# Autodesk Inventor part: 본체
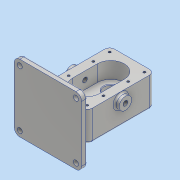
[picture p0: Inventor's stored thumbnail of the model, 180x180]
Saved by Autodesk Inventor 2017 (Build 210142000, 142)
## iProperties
Part Number: 본체
Material: 알루미늄 6061
Document SubType Name: Modeling
Designer: MRC
Density: 2.7 g/cm^3
Appearance: 알루미늄 - 평지
Mass: 1537.14 g
Surface Area: 869.879 cm^2
Volume: 569.31 cm^3
Author: MRC
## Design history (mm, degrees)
sketch "스케치1"
  geometry: L1 (40, -60)-(-40, -60); L2 (-40, -60)-(-40, 60); L3 (-40, 60)-(40, 60); L4 (40, 60)-(40, -60); L5 (40, -60)-(-40, 60); L6 (-40, -60)-(40, 60); 1 further point
  constraints: 12 end point, 2 midpoint, 2 parallel, 1 horizontal, 1 perpendicular
  dimensions: "d0" = 80 distance of L2.end L3.end; "d1" = 120 distance of L1.end L2.end
extrude "돌출1" new body sketch "스케치1" distance "d2" = 14; taper "d4" = 0 deg; dims "d3" = 39, "d5" = 0
fillet "모깎기1" dims "d6" = 9
sketch "스케치2"
  geometry: L1 (0, -22)-(0, 22); L2 (-24, -22)-(-24, 22); L3 (24, 22)-(24, -22); A1 r 24 centre (0, -22) between (-24, -22) and (24, -22); A2 r 24 centre (0, 22) between (24, 22) and (-24, 22); 1 further point
  constraints: 8 end point, 4 point on circle, 4 tangent, 2 centre point, 1 midpoint, 1 parallel, 1 vertical
  dimensions: "d7" = 24 radius of A2; "d8" = 44 distance of L3.start L3.end
extrude "돌출2" cut sketch "스케치2" distance "d9" = 29; taper "d10" = 0 deg
sketch "스케치4"
  geometry: C1 r 19 at (0, 22); A1 r 24 centre (0, 22) between (24, 22) and (-24, 22) reference; 1 further point
  constraints: 1 centre point, 1 concentric
  dimensions: "d11" = 38 diameter of C1
extrude "돌출3" join sketch "스케치4" distance "d12" = 17; taper "d13" = 0 deg
hole "구멍1" diameter "d16" = 17; stored, may be unused: countersink angle "d20" = 90 deg, drill point angle "d22" = 118 deg; dims "d14" = 10, "d15" = 10, "d17" = 6, "d18" = 28, "d19" = 7.3, "d21" = 8
sketch "스케치5"
  geometry: C1 r 8.5 at (0, 22) reference; C2 r 12.5 at (0, 22); C3 r 12.5 at (0, -22); A1 r 24 centre (0, -22) between (-24, -22) and (24, -22) reference; A2 r 24 centre (0, 22) between (24, 22) and (-24, 22) reference; 1 further point
  constraints: 2 centre point, 2 coincident
  dimensions: "d23" = 25 diameter of C2; "d24" = 25 diameter of C3
extrude "돌출4" cut sketch "스케치5" distance "d25" = 15; taper "d26" = 0 deg
fillet "모깎기2" dims "d27" = 0.5
chamfer "모따기1" distance "d28" = 0.7; stored, may be unused: second distance "d29" = 2, angle "d30" = 30 deg
fillet "모깎기3" dims "d31" = 3
sketch "스케치6"
  geometry: C1 r 11 at (14, 51); 1 further point
  constraints: 1 centre point, 1 coincident
  dimensions: "d32" = 22 diameter of C1
extrude "돌출5" join sketch "스케치6" distance "d33" = 8; taper "d34" = 0 deg
hole "구멍2" diameter "d37" = 8.376; stored, may be unused: countersink angle "d41" = 90 deg, drill point angle "d43" = 118 deg; dims "d35" = 10, "d36" = 10, "d38" = 20, "d39" = 28, "d40" = 7.3, "d42" = 27.3
fillet "모깎기5" dims "d45" = 3
sketch "스케치7"
  geometry: A1 r 9 centre (31, -51) between (31, -60) and (40, -51) reference; A2 r 9 centre (31, 51) between (40, 51) and (31, 60) reference; A3 r 9 centre (-31, 51) between (-31, 60) and (-40, 51) reference; A4 r 9 centre (-31, -51) between (-40, -51) and (-31, -60) reference; 9 further points
  constraints: 4 coincident, 4 vertical alignment, 2 horizontal alignment
  dimensions: "d46" = 29 distance of point (-31, 22) point (-31, 51); "d47" = 29 distance of point (31, -22) point (31, -51)
hole "구멍3" sketch "스케치7" at (-31, 51), (31, 51), (31, -51), (-31, -51), (-31, 22), (-31, -22), (31, 22), (31, -22) diameter "d48" = 4.134; stored, may be unused: countersink angle "d52" = 90 deg, drill point angle "d54" = 118 deg; dims "d49" = 10, "d50" = 28, "d51" = 7.3, "d53" = 12
sketch "스케치8"
  geometry: L1 (-80, 64)-(-90, 64); L2 (-90, 64)-(-90, -56); L3 (-90, -56)-(-80, -56); L4 (-80, -56)-(-80, 64); L5 (60, -36)-(60, 14) reference; L6 (3, -56)-(41, -56) reference; L7 (-80, -39)-(-60, -27.453); L8 (-80, 14)-(-60, 2.453); L9 (-60, -36)-(-60, 14) reference; 1 further point
  constraints: 12 end point, 4 point on line, 2 parallel, 1 horizontal, 1 perpendicular
  dimensions: "d55" = 120 distance of L1.end L2.end; "d56" = 150 distance between parallel lines of L5 L2; "d57" = 10 distance of L2.end L3.end; "d58" = 0 distance between parallel lines of L3 L6; "d59" = 53 distance of L8.start L7.start; "d60" = 17 distance from line of L3 L7.start; "d61" = 60 deg angle of L4 L7; "d62" = 60 deg angle of L4 L8
extrude "돌출6" join sketch "스케치8" stored distance "d63" = 120; taper "d64" = 0 deg
extrude "돌출7" join sketch "스케치8" stored distance "d65" = 48; taper "d66" = 0 deg
fillet "모깎기6" dims "d67" = 10
fillet "모깎기7" dims "d68" = 3
fillet "모깎기8" dims "d69" = 3
sketch "스케치9"
  geometry: A1 r 7 centre (100, -7) between (107, -7) and (100, 0) reference; A2 r 7 centre (0, -7) between (0, 0) and (-7, -7) reference; A3 r 7 centre (0, -107) between (-7, -107) and (0, -114) reference; A4 r 7 centre (100, -107) between (100, -114) and (107, -107) reference; 5 further points
  constraints: 4 coincident
hole "구멍4" sketch "스케치9" at (0, -7), (100, -7), (100, -107), (0, -107) diameter "d70" = 9; stored, may be unused: countersink angle "d74" = 90 deg, drill point angle "d76" = 118 deg; dims "d71" = 10, "d72" = 28, "d73" = 7.3, "d75" = 9
chamfer "모따기2" distance "d77" = 1; stored, may be unused: second distance "d78" = 2, angle "d79" = 30 deg
sketch "스케치10"
  geometry: L1 (0, -117)-(100, -117) reference; L2 (-10, -7)-(-10, -107) reference; 2 further points
  constraints: 1 other
  dimensions: "d80" = 10 distance from line of point (50, -107) L1; "d81" = 60 distance from line of point (50, -107) L2
feature "엠보싱1" sketch "스케치10" dims "d0" = 80, "d1" = 120, "d82" = 0.5, "d83" = 0
fillet "모깎기9" dims "d84" = 3
node "솔리드1"
mirror "미러1"
